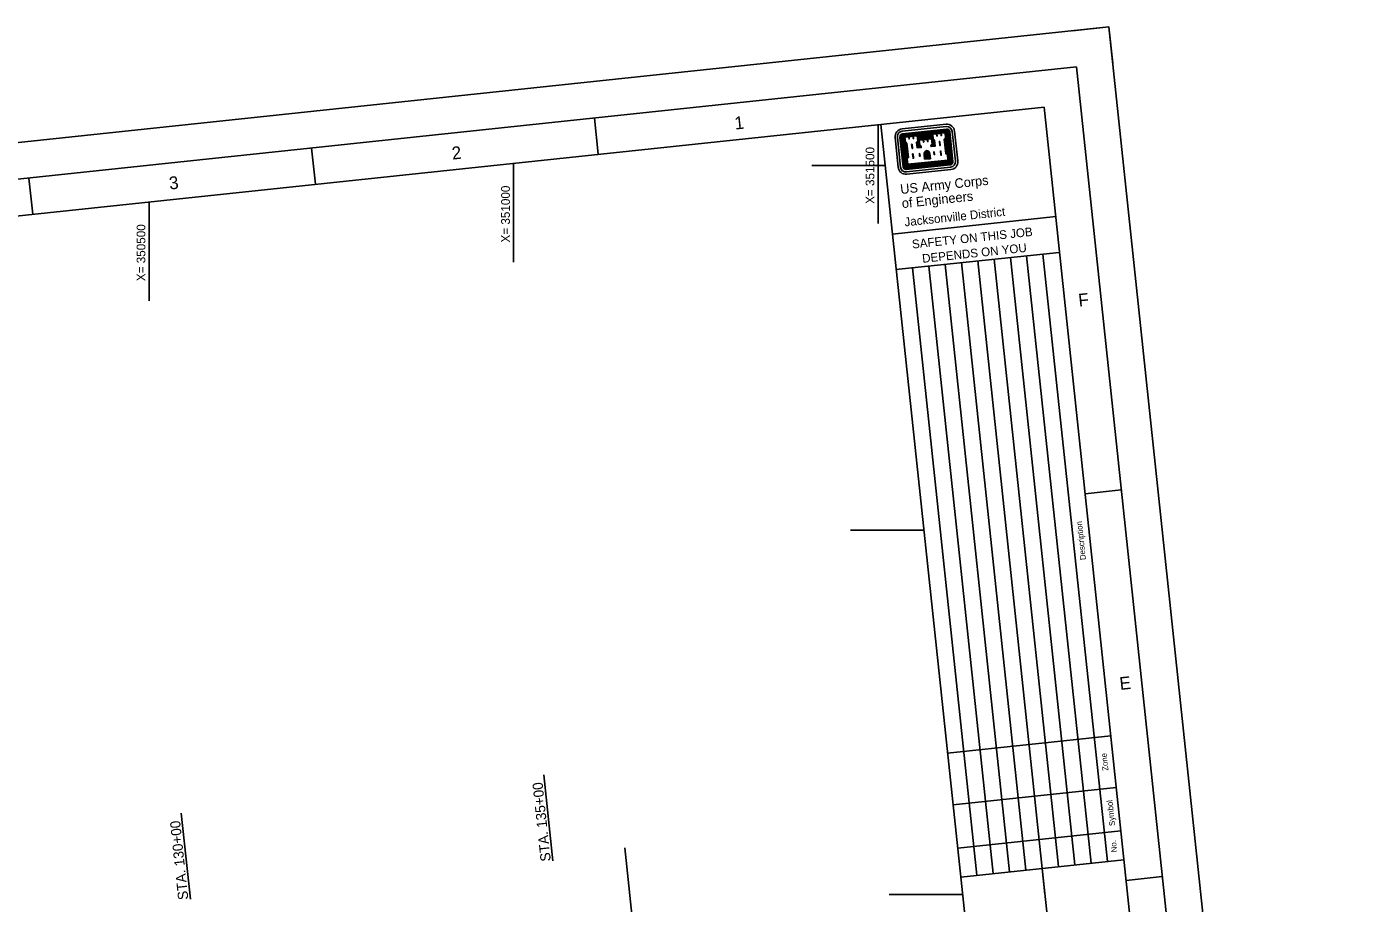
# Model space of a CAD drawing. Extents: x 347441 to 352175, y 1184845 to 1188690.
# Drawn here: x 350332 to 352175, y 1187488 to 1188690 of the extents above; entities that cross this region are included whole.
import ezdxf

# ---------------------------------------------------------------- set-up
doc = ezdxf.new("R2010")
doc.units = 0
for name, color, linetype in [('G-ANNO-NPLT', 7, 'Continuous'), ('G-ANNO-TEXT-LOGO', 7, 'Continuous'), ('G-ANNO-TEXT-TTLB', 7, 'Continuous'), ('G-ANNO-TTLB', 7, 'Continuous'), ('V-ALGN-TEXT', 7, 'Continuous'), ('V-ANNO-MATC', 7, 'Continuous'), ('V-TOPO-COOR-STAT', 7, 'Continuous')]:
    doc.layers.add(name, color=color, linetype=linetype)

msp = doc.modelspace()

# ---------------------------------------------------------------- linework, layer by layer
at = {"layer": 'G-ANNO-NPLT'}
msp.add_lwpolyline([(347441.2, 1188226.4), (351816.7, 1188690.2), (352175, 1185309.2), (347799.6, 1184845.4)], close=True, dxfattribs=at)
msp.add_lwpolyline([(351821.9, 1188640.5), (351816.7, 1188690.2), (351766.9, 1188685)], dxfattribs=at)
at = {"layer": 'G-ANNO-TEXT-LOGO'}
for p, q in [((351593.4, 1188556.6), (351532.9, 1188550.2)), ((351533.2, 1188547), (351593.7, 1188553.4)), ((351594.1, 1188550), (351533.6, 1188543.6)), ((351594.2, 1188549.1), (351533.7, 1188542.7)), ((351594.3, 1188548.2), (351533.8, 1188541.8)), ((351594.3, 1188547.4), (351533.9, 1188541)), ((351594.4, 1188546.5), (351534, 1188540.1)), ((351555, 1188541.5), (351573.5, 1188543.5)), ((351555.1, 1188540.6), (351573.6, 1188542.6)), ((351555.2, 1188539.8), (351573.7, 1188541.8)), ((351593.3, 1188545.8), (351597.5, 1188506.2)), ((351594.1, 1188545.9), (351598.4, 1188505.4)), ((351595, 1188546), (351599.3, 1188505.2)), ((351595.9, 1188546.1), (351600.2, 1188505.3)), ((351596.7, 1188546.2), (351601, 1188505.4)), ((351597.6, 1188546.2), (351601.9, 1188505.5)), ((351598.5, 1188546.3), (351602.8, 1188505.6)), ((351601.9, 1188546.7), (351606.2, 1188505.9)), ((351609.5, 1188506.3), (351605.1, 1188547)), ((351523.4, 1188538.4), (351527.7, 1188497.6)), ((351530.9, 1188497.9), (351526.6, 1188538.7)), ((351530.1, 1188539.1), (351534.4, 1188498.3)), ((351531, 1188539.2), (351535.3, 1188498.4)), ((351531.8, 1188539.3), (351536.1, 1188498.5)), ((351532.6, 1188539.4), (351537, 1188498.6)), ((351533.5, 1188539.5), (351537.9, 1188498.7)), ((351534.4, 1188539.6), (351538.7, 1188499.1)), ((351535.2, 1188539.6), (351539.4, 1188500.1)), ((351536.8, 1188531.1), (351539.1, 1188510.2)), ((351537.8, 1188530.3), (351539.8, 1188511.3)), ((351555.3, 1188539), (351573.8, 1188540.9)), ((351555.4, 1188538.1), (351573.9, 1188540)), ((351555.5, 1188537.3), (351574, 1188539.2)), ((351555.6, 1188536.4), (351574.1, 1188538.3)), ((351592.7, 1188536.1), (351594.7, 1188517.1)), ((351593.5, 1188537), (351595.7, 1188516.3)), ((351598.4, 1188505.4), (351538.7, 1188499.1)), ((351597.5, 1188506.2), (351539.4, 1188500.1)), ((351563.9, 1188508.6), (351563.2, 1188515.2)), ((351563.9, 1188508.6), (351571.8, 1188509.4)), ((351564.7, 1188508.7), (351564, 1188515.3)), ((351565.6, 1188508.8), (351564.8, 1188515.4)), ((351566.5, 1188508.9), (351565.7, 1188515.5)), ((351567.2, 1188508.9), (351566.5, 1188515.6)), ((351568.4, 1188509.1), (351567.7, 1188515.7)), ((351569.2, 1188509.2), (351568.5, 1188515.8)), ((351570.1, 1188509.2), (351569.4, 1188515.9)), ((351571, 1188509.3), (351570.3, 1188516)), ((351571.8, 1188509.4), (351571.1, 1188516.1)), ((351598.9, 1188504.6), (351538.4, 1188498.1)), ((351599, 1188503.8), (351538.5, 1188497.3)), ((351599.1, 1188502.9), (351538.6, 1188496.5)), ((351599.2, 1188502), (351538.7, 1188495.6)), ((351599.2, 1188501.2), (351538.8, 1188494.8)), ((351599.6, 1188497.7), (351539.2, 1188491.3)), ((351539.5, 1188488), (351600, 1188494.4))]:
    msp.add_line(p, q, dxfattribs=at)
for points in [[(351535.9, 1188539.7), (351536.8, 1188531.9), (351538.6, 1188530.3), (351540.6, 1188511.4), (351539.1, 1188509.4), (351540.1, 1188500.7), (351596.7, 1188506.7), (351595.8, 1188515.4), (351593.8, 1188517), (351591.8, 1188536), (351593.4, 1188537.9), (351592.6, 1188545.7), (351585.2, 1188544.9), (351579.4, 1188544.3), (351574, 1188543.7), (351574.8, 1188535.9), (351576.9, 1188534.4), (351577.7, 1188527.4), (351573.5, 1188527), (351573.4, 1188527.7), (351575, 1188529.7), (351574.2, 1188537.4), (351566.7, 1188536.6), (351561, 1188536), (351555.7, 1188535.5), (351556.5, 1188527.7), (351558.5, 1188526.1), (351558.6, 1188525.4), (351554.4, 1188525), (351553.6, 1188531.9), (351555.3, 1188533.8), (351554.4, 1188541.7), (351547, 1188540.9), (351541.2, 1188540.3), (351535.9, 1188539.7)], [(351536.8, 1188538.9), (351537.5, 1188532.3), (351539.5, 1188530.7), (351541.6, 1188511), (351540, 1188509.1), (351540.8, 1188501.7), (351595.9, 1188507.5), (351595.1, 1188514.9), (351593, 1188516.5), (351590.9, 1188536.2), (351592.6, 1188538.2), (351591.9, 1188544.7), (351586.5, 1188544.2), (351586.9, 1188541.1), (351586.4, 1188541), (351586, 1188544.1), (351580.8, 1188543.6), (351581.1, 1188540.5), (351580.7, 1188540.4), (351580.4, 1188543.5), (351575, 1188542.9), (351575.7, 1188536.4), (351577.7, 1188534.8), (351578.5, 1188526.7), (351572.8, 1188526.1), (351572.6, 1188528), (351574.2, 1188530), (351573.5, 1188536.6), (351568.1, 1188536), (351568.4, 1188532.9), (351568, 1188532.9), (351567.7, 1188535.9), (351562.3, 1188535.4), (351562.7, 1188532.3), (351562.2, 1188532.2), (351561.8, 1188535.3), (351556.6, 1188534.8), (351557.3, 1188528.2), (351559.2, 1188526.6), (351559.4, 1188524.7), (351553.7, 1188524.1), (351552.8, 1188532.1), (351554.4, 1188534.1), (351553.7, 1188540.7), (351548.5, 1188540.1), (351548.8, 1188537.1), (351548.3, 1188537), (351548, 1188540.1), (351542.6, 1188539.5), (351542.9, 1188536.4), (351542.5, 1188536.4), (351542.2, 1188539.5), (351536.8, 1188538.9)], [(351546.1, 1188529.1), (351546.7, 1188523.4), (351547.3, 1188523.4), (351546.7, 1188529.2), (351546.1, 1188529.1)], [(351555, 1188532.2), (351554.6, 1188531.6), (351555.2, 1188526), (351557.1, 1188526.2), (351555.6, 1188527.3), (351555.1, 1188532.3)], [(351575.5, 1188534.4), (351576.1, 1188533.9), (351576.7, 1188528.2), (351574.9, 1188528.1), (351575.9, 1188529.5), (351575.4, 1188534.4)], [(351584.8, 1188533.2), (351585.4, 1188527.5), (351584.9, 1188527.4), (351584.3, 1188533.2), (351584.8, 1188533.2)], [(351547.5, 1188515.9), (351548.1, 1188510), (351548.7, 1188510.1), (351548.1, 1188516), (351547.5, 1188515.9)], [(351556.7, 1188516.9), (351557.1, 1188512.8), (351557.6, 1188512.8), (351557.1, 1188516.9), (351556.7, 1188516.9)], [(351577.1, 1188519), (351577.6, 1188515), (351577.1, 1188514.9), (351576.6, 1188519), (351577.1, 1188519)], [(351586.2, 1188520), (351586.8, 1188514.1), (351586.3, 1188514.1), (351585.7, 1188519.9), (351586.2, 1188520)]]:
    msp.add_lwpolyline(points, dxfattribs=at)
for centre, major_axis, start_param, end_param in [((351534.1, 1188539.5), (10.7, 1.1), 1.57078, 3.141576), ((351534.1, 1188539.5), (7.45, 0.79), 1.57078, 3.141576), ((351534.1, 1188539.5), (4, 0.42), 1.57078, 3.141576), ((351534.1, 1188539.5), (3.13, 0.33), 1.57078, 3.141576), ((351534.1, 1188539.5), (2.27, 0.24), 1.57078, 3.141576), ((351594.4, 1188545.9), (10.7, 1.1), 6.283169, 7.853965), ((351594.4, 1188545.9), (7.45, 0.79), 6.28317, 7.853966), ((351594.4, 1188545.9), (4, 0.42), 6.283169, 7.853965), ((351594.4, 1188545.9), (3.13, 0.33), 6.283169, 7.853965), ((351594.4, 1188545.9), (2.27, 0.24), 6.283169, 7.853965), ((351594.4, 1188545.9), (1.41, 0.15), 6.283169, 7.853965), ((351594.4, 1188545.9), (0.543, 0.058), 6.283169, 7.853965), ((351534.1, 1188539.5), (1.41, 0.15), 1.57078, 3.141576), ((351534.1, 1188539.5), (0.543, 0.058), 1.57078, 3.141576), ((351568.7, 1188515.4), (-5.52, -0.59), 4.985832, 6.214359), ((351568.7, 1188515.4), (-4.66, -0.49), 4.947465, 6.21436), ((351568.7, 1188515.4), (-3.8, -0.4), 4.947465, 6.21436), ((351568.7, 1188515.4), (-2.93, -0.31), 4.947465, 6.21436), ((351565.7, 1188515.1), (2.07, 0.22), 0.068794, 1.335689), ((351565.7, 1188515.1), (2.93, 0.31), 0.068794, 1.335689), ((351565.7, 1188515.1), (3.8, 0.4), 0.068795, 1.335689), ((351565.7, 1188515.1), (4.66, 0.49), 0.068795, 1.335689), ((351568.7, 1188515.4), (-2.07, -0.22), 4.947465, 6.214359), ((351565.7, 1188515.1), (5.52, 0.59), 0.068795, 1.29842), ((351598.8, 1188505.1), (0.543, 0.058), 4.712373, 6.28317), ((351598.8, 1188505.1), (1.41, 0.15), 4.712373, 6.28317), ((351598.8, 1188505.1), (2.27, 0.24), 4.712373, 6.28317), ((351598.8, 1188505.1), (3.13, 0.33), 4.712373, 6.28317), ((351598.8, 1188505.1), (4, 0.42), 4.712373, 6.28317), ((351598.8, 1188505.1), (-7.45, -0.79), 1.570781, 3.141577), ((351598.8, 1188505.1), (10.7, 1.1), 4.712373, 6.28317), ((351538.4, 1188498.7), (-10.7, -1.1), 6.28317, 7.853966), ((351538.4, 1188498.7), (-7.45, -0.79), 6.28317, 7.853966), ((351538.4, 1188498.7), (-4, -0.42), 6.28317, 7.853966), ((351538.4, 1188498.7), (-3.13, -0.33), 6.28317, 7.853966), ((351538.4, 1188498.7), (-2.27, -0.24), 6.28317, 7.853966), ((351538.4, 1188498.7), (-1.41, -0.15), 6.28317, 7.853966), ((351538.4, 1188498.7), (-0.543, -0.058), 6.28317, 7.853966)]:
    msp.add_ellipse(centre, major_axis=major_axis, ratio=0.99964, start_param=start_param, end_param=end_param, dxfattribs=at)
at = {"layer": 'G-ANNO-TTLB'}
for p, q in [((351110.9, 1188565.1), (351116.2, 1188515.4)), ((351504, 1188556.5), (351841.3, 1185374.4)), ((350723.1, 1188524), (350728.4, 1188474.3)), ((350335.3, 1188482.9), (350340.5, 1188433.2)), ((351520, 1188406.1), (351743.7, 1188429.9)), ((351524.5, 1188357.2), (351748.3, 1188380.9)), ((351703.9, 1188376.2), (351792.3, 1187543)), ((351726.3, 1188378.6), (351814.6, 1187545.4)), ((351547.3, 1188359.6), (351635.6, 1187526.4)), ((351569.7, 1188362), (351658, 1187528.8)), ((351592.1, 1188364.4), (351680.4, 1187531.1)), ((351614.4, 1188366.8), (351702.8, 1187533.5)), ((351636.8, 1188369.1), (351725.1, 1187535.9)), ((351659.2, 1188371.5), (351747.5, 1187538.3)), ((351681.6, 1188373.9), (351769.9, 1187540.6)), ((351833.7, 1188055), (351784, 1188049.7)), ((351595.4, 1187694.1), (351819.2, 1187717.8)), ((351602.9, 1187623.3), (351826.7, 1187647.1)), ((351609.3, 1187563.7), (351833, 1187587.3)), ((351613.5, 1187524), (351837.2, 1187547.8)), ((351815.3, 1186681.1), (351725.3, 1187535.9)), ((351725.3, 1187535.9), (351729, 1187500.7)), ((351889.9, 1187524.7), (351840.2, 1187519.4))]:
    msp.add_line(p, q, dxfattribs=at)
for points in [[(347844, 1184900.4), (352120.1, 1185353.6), (351772.2, 1188635.2), (347496.2, 1188182)], [(351727.8, 1188580.2), (347625.8, 1188145.4), (347963.1, 1184963.3), (352065.1, 1185398.1)]]:
    msp.add_lwpolyline(points, close=True, dxfattribs=at)
at = {"layer": 'V-ALGN-TEXT'}
for p, q in [((351053.9, 1187546.5), (351041.4, 1187664.4)), ((350556.7, 1187493.8), (350544.2, 1187611.7))]:
    msp.add_line(p, q, dxfattribs=at)
at = {"layer": 'V-ANNO-MATC'}
msp.add_line((351289.7, 1186271.2), (351152.6, 1187564), dxfattribs=at)
at = {"layer": 'V-TOPO-COOR-STAT'}
for p, q in [((351500, 1188420.3), (351500, 1188556.1)), ((351000, 1188367.3), (351000, 1188503.1)), ((351409.4, 1188500), (351510, 1188500)), ((350500, 1188314.3), (350500, 1188450.1)), ((351462.4, 1188000), (351563, 1188000)), ((351515.4, 1187500), (351616, 1187500))]:
    msp.add_line(p, q, dxfattribs=at)

# ---------------------------------------------------------------- texts
at = {"layer": 'G-ANNO-TEXT-TTLB'}
for s, height, rotation, p in [('US Army Corps', 13.086, 6.0506, (351531.2, 1188460.9)), ('of Engineers', 13.086, 6.0506, (351533.3, 1188441.6)), ('Jacksonville District', 11.9, 6.0506, (351536.9, 1188416.5)), ('SAFETY ON THIS JOB', 11.9, 6.0506, (351547.3, 1188386.1)), ('DEPENDS ON YOU', 11.9, 6.0506, (351561.2, 1188366.5)), ('Description', 8, 96.0506, (351785.2, 1187959.3)), ('Zone', 8, 96.0506, (351816.1, 1187670.2)), ('Symbol', 8, 96.0506, (351825.3, 1187594.5)), ('No.', 8, 96.0506, (351828.1, 1187558.4))]:
    msp.add_text(s, height=height, rotation=rotation, dxfattribs=at).set_placement(p)
at = {"layer": 'G-ANNO-TTLB'}
for s, p in [('1', (351304.1, 1188549.3)), ('2', (350916.3, 1188508.1)), ('3', (350528.4, 1188467)), ('F', (351775.7, 1188306.4)), ('E', (351832.2, 1187780.6))]:
    msp.add_text(s, height=17.5, rotation=6.0506, dxfattribs=at).set_placement(p)
at = {"layer": 'V-ALGN-TEXT'}
for s, p in [('STA. 135+00', (351051.2, 1187546.1)), ('STA. 130+00', (350554, 1187493.4))]:
    msp.add_text(s, height=13.92, rotation=96.0506, dxfattribs=at).set_placement(p)
at = {"layer": 'V-TOPO-COOR-STAT'}
for s, p in [('X= 351500', (351495, 1188447.4)), ('X= 351000', (350995, 1188394.4)), ('X= 350500', (350495, 1188341.4))]:
    msp.add_text(s, height=12, rotation=90, dxfattribs=at).set_placement(p)

doc.saveas('drawing.dxf')
